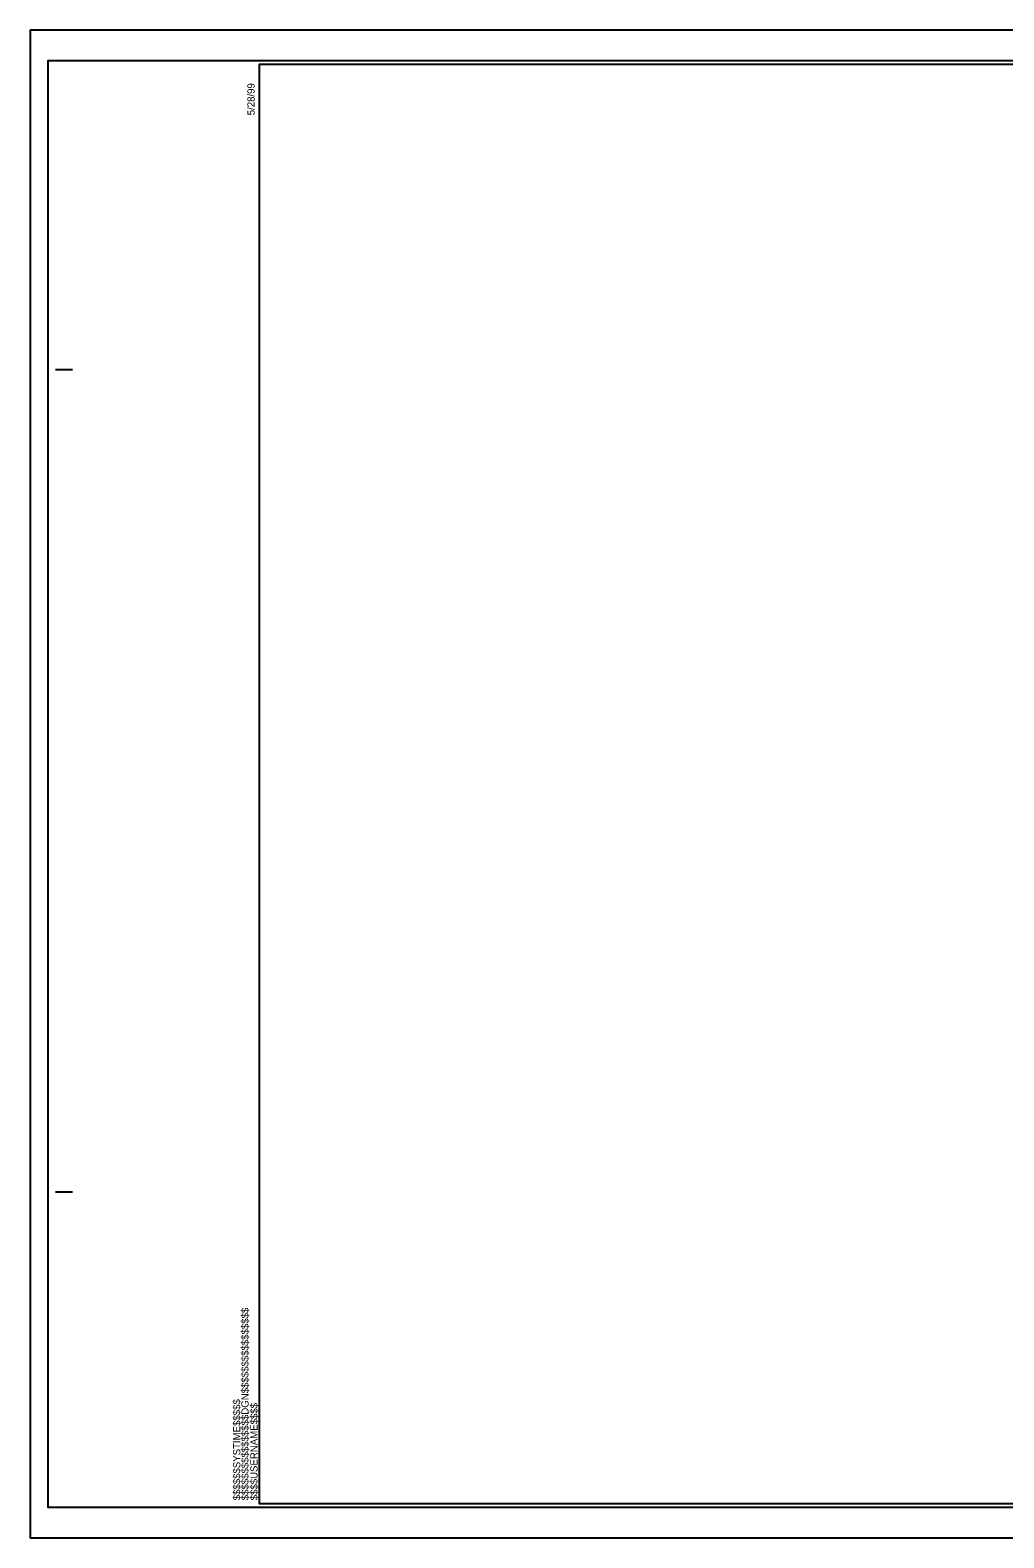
# Model space of a CAD drawing. Extents: x 573898.1 to 573931.8, y -53269.2 to -53247.2.
# Drawn here: x 573898.09 to 573912.29, y -53269.22 to -53247.22 of the extents above; entities that cross this region are included whole.
import ezdxf

# ---------------------------------------------------------------- set-up
doc = ezdxf.new("R2010")
doc.units = 0
for name, color, linetype in [('Sheet Cutting Line CELL', 7, 'Continuous'), ('Sheet Plot Border Inside CELL', 7, 'Continuous'), ('Sheet Plot Border Outside CELL', 7, 'Continuous'), ('Sheet Summary CELL', 7, 'Continuous')]:
    doc.layers.add(name, color=color, linetype=linetype)

msp = doc.modelspace()

# ---------------------------------------------------------------- linework, layer by layer
at = {"layer": 'Sheet Cutting Line CELL'}
for p, q in [((573931.766, -53247.225), (573898.086, -53247.225)), ((573898.086, -53247.225), (573898.086, -53269.225)), ((573898.086, -53269.225), (573931.766, -53269.225))]:
    msp.add_line(p, q, dxfattribs=at)
at = {"layer": 'Sheet Plot Border Inside CELL'}
msp.add_lwpolyline([(573931.676, -53247.674), (573898.346, -53247.674), (573898.346, -53268.776), (573931.676, -53268.776)], close=True, dxfattribs=at)
at = {"layer": 'Sheet Plot Border Outside CELL'}
msp.add_lwpolyline([(573931.766, -53247.225), (573898.086, -53247.225), (573898.086, -53269.225), (573931.766, -53269.225)], close=True, dxfattribs=at)
at = {"layer": 'Sheet Summary CELL'}
for p, q in [((573901.426, -53247.725), (573901.426, -53248.534)), ((573898.456, -53252.175), (573898.706, -53252.175)), ((573898.456, -53264.175), (573898.706, -53264.175)), ((573901.426, -53268.725), (573901.426, -53268.725)), ((573901.426, -53268.725), (573901.426, -53268.725)), ((573901.426, -53268.725), (573901.426, -53268.725)), ((573901.426, -53268.725), (573901.426, -53268.725)), ((573901.426, -53268.725), (573901.426, -53268.725)), ((573901.426, -53268.725), (573901.426, -53268.725))]:
    msp.add_line(p, q, dxfattribs=at)
msp.add_lwpolyline([(573931.426, -53247.725), (573901.426, -53247.725), (573901.426, -53268.725), (573931.426, -53268.725)], close=True, dxfattribs=at)
msp.add_lwpolyline([(573904.176, -53268.725), (573904.176, -53268.725)], dxfattribs=at)

# ---------------------------------------------------------------- texts
for s, p in [('5/28/99', (573901.361, -53248.467)), ('$$$$$$$$$$$$$$$$DGN$$$$$$$$$$$$$$$$', (573901.273, -53268.677)), ('$$$$$$SYSTIME$$$$$', (573901.152, -53268.677)), ('$$$$USERNAME$$$$', (573901.404, -53268.677))]:
    msp.add_text(s, height=0.105, rotation=90, dxfattribs=at).set_placement(p)

doc.saveas('drawing.dxf')
